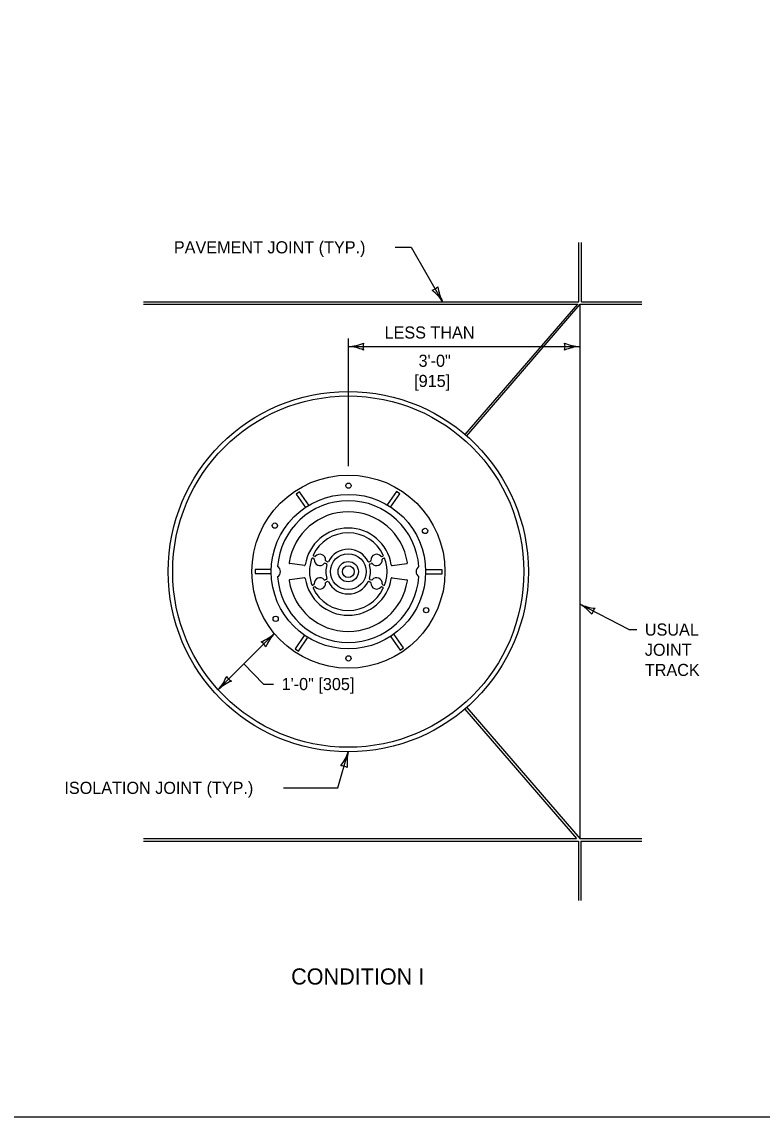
# Model space of a CAD drawing. Extents: x 49991.4 to 50021, y 49987.6 to 50011.4.
# Drawn here: x 50006.05 to 50009.72, y 49987.8 to 49993.22 of the extents above; entities that cross this region are included whole.
import ezdxf

# ---------------------------------------------------------------- set-up
doc = ezdxf.new("R2010")
doc.units = 0
for name, color, linetype in [('Level 1', 7, 'Continuous'), ('Level 15', 7, 'Continuous'), ('Level 2', 7, 'Continuous'), ('Level 3', 7, 'Continuous'), ('Level 62', 7, 'Continuous'), ('W35', 7, 'Continuous')]:
    doc.layers.add(name, color=color, linetype=linetype)

msp = doc.modelspace()

# ---------------------------------------------------------------- linework, layer by layer
at = {"layer": 'Level 1'}
for p, q in [((50008.8099, 49991.838), (50008.8099, 49992.1307)), ((50008.8219, 49991.838), (50008.8219, 49992.1307)), ((50006.6519, 49991.838), (50008.8099, 49991.838)), ((50006.6519, 49991.826), (50008.8044, 49991.826)), ((50008.2465, 49991.1797), (50008.8044, 49991.826)), ((50008.2536, 49991.1736), (50008.8167, 49991.826)), ((50008.8146, 49991.8236), (50008.8146, 49989.1782)), ((50008.8167, 49991.826), (50009.1209, 49991.826)), ((50008.8219, 49991.838), (50009.1209, 49991.838)), ((50007.4491, 49990.5314), (50007.3769, 49990.5416)), ((50007.4961, 49990.5654), (50007.4907, 49990.5676)), ((50007.5004, 49990.5759), (50007.495, 49990.5781)), ((50007.5591, 49990.5393), (50007.5523, 49990.5421)), ((50007.5635, 49990.5498), (50007.5566, 49990.5526)), ((50007.77, 49990.5498), (50007.7768, 49990.5526)), ((50007.7743, 49990.5393), (50007.7812, 49990.5421)), ((50007.833, 49990.5759), (50007.8385, 49990.5781)), ((50007.8374, 49990.5654), (50007.8428, 49990.5676)), ((50007.8844, 49990.5314), (50007.9566, 49990.5416)), ((50007.4491, 49990.4703), (50007.3769, 49990.4601)), ((50007.4961, 49990.4363), (50007.4907, 49990.4341)), ((50007.5591, 49990.4624), (50007.5523, 49990.4596)), ((50007.5635, 49990.4519), (50007.5566, 49990.4491)), ((50007.77, 49990.4519), (50007.7768, 49990.4491)), ((50007.7743, 49990.4624), (50007.7812, 49990.4596)), ((50007.8374, 49990.4363), (50007.8428, 49990.4341)), ((50007.8844, 49990.4703), (50007.9566, 49990.4601)), ((50007.5004, 49990.4258), (50007.495, 49990.4236)), ((50007.833, 49990.4258), (50007.8385, 49990.4236)), ((50008.2445, 49989.8203), (50008.7986, 49989.1783)), ((50008.2536, 49989.8281), (50008.8145, 49989.1783)), ((50006.6519, 49989.1783), (50008.7986, 49989.1783)), ((50006.6519, 49989.1663), (50008.8073, 49989.1663)), ((50008.8073, 49989.1663), (50008.8073, 49988.871)), ((50008.8145, 49989.1783), (50009.1209, 49989.1783)), ((50008.8193, 49989.1663), (50009.1209, 49989.1663)), ((50008.8193, 49989.1663), (50008.8193, 49988.871))]:
    msp.add_line(p, q, dxfattribs=at)
msp.add_lwpolyline([(49999.3835, 49998.9992), (50016.7501, 49998.9992), (50016.7501, 49987.7988), (49999.3835, 49987.7988)], close=True, dxfattribs=at)
for points in [[(50007.4706, 49990.8307), (50007.4246, 49990.8963), (50007.4082, 49990.8848), (50007.4542, 49990.8192)], [(50007.4706, 49990.8307), (50007.4246, 49990.8963), (50007.4082, 49990.8848), (50007.4542, 49990.8192)], [(50007.8755, 49990.8208), (50007.9215, 49990.8864), (50007.9051, 49990.8979), (50007.8591, 49990.8323)], [(50007.8755, 49990.8208), (50007.9215, 49990.8864), (50007.9051, 49990.8979), (50007.8591, 49990.8323)], [(50007.285, 49990.5113), (50007.2049, 49990.5113), (50007.2049, 49990.4913), (50007.285, 49990.4913)], [(50008.0524, 49990.4903), (50008.1325, 49990.4903), (50008.1325, 49990.5103), (50008.0524, 49990.5103)], [(50007.4488, 49990.1844), (50007.4029, 49990.1188), (50007.4193, 49990.1073), (50007.4652, 49990.173)], [(50007.4488, 49990.1844), (50007.4029, 49990.1188), (50007.4193, 49990.1073), (50007.4652, 49990.173)], [(50007.8782, 49990.1784), (50007.9242, 49990.1127), (50007.9406, 49990.1242), (50007.8946, 49990.1898)], [(50007.8782, 49990.1784), (50007.9242, 49990.1127), (50007.9406, 49990.1242), (50007.8946, 49990.1898)]]:
    msp.add_lwpolyline(points, dxfattribs=at)
for centre, radius in [((50007.6667, 49990.5009), 0.8927), ((50007.6667, 49990.5009), 0.8702), ((50007.6676, 49990.5011), 0.4784), ((50007.6676, 49990.5011), 0.4784), ((50007.6676, 49990.9269), 0.0131), ((50007.6676, 49990.5011), 0.3827), ((50007.6676, 49990.5011), 0.3827), ((50007.303, 49990.7289), 0.0131), ((50008.0475, 49990.7025), 0.0131), ((50007.6667, 49990.5009), 0.0888), ((50007.6667, 49990.5009), 0.0503), ((50007.6667, 49990.5009), 0.0293), ((50008.0528, 49990.3102), 0.0131), ((50007.307, 49990.267), 0.0131), ((50007.6676, 49990.0711), 0.0131)]:
    msp.add_circle(centre, radius, dxfattribs=at)
for centre, radius, start, end in [((50007.6667, 49990.5009), 0.3512, 4.1368, 175.8632), ((50007.6667, 49990.5009), 0.2965, 8.7492, 171.2508), ((50007.6667, 49990.5009), 0.216, 8.9977, 171.0023), ((50007.6667, 49990.5009), 0.1922, 90, 154.6354), ((50007.6667, 49990.5009), 0.1922, 25.3646, 90), ((50007.6667, 49990.5009), 0.1107, 90, 152.7811), ((50007.6667, 49990.5009), 0.1107, 27.2189, 90), ((50007.3774, 49990.5454), 0.00383, 171.2515, 262.0006), ((50007.6667, 49990.5009), 0.1922, 160.3645, 179.9999), ((50007.4892, 49990.5642), 0.00374, 67.5005, 160.3653), ((50007.4964, 49990.5816), 0.00374, 154.6345, 247.5005), ((50007.4947, 49990.5619), 0.00374, 354.7032, 67.5005), ((50007.5264, 49990.559), 0.0281, 174.704, 320.2958), ((50007.5019, 49990.5793), 0.00374, 247.5005, 320.2976), ((50007.5264, 49990.559), 0.0281, 354.7044, 140.2958), ((50007.5509, 49990.5387), 0.00374, 67.5005, 140.2976), ((50007.5581, 49990.5561), 0.00374, 174.7032, 247.5005), ((50007.5649, 49990.5532), 0.00374, 247.5005, 332.7814), ((50007.7685, 49990.5532), 0.00374, 207.2186, 292.4995), ((50007.7754, 49990.5561), 0.00374, 292.501, 5.2969), ((50007.8071, 49990.559), 0.0281, 39.7042, 185.2956), ((50007.7826, 49990.5387), 0.00374, 39.7034, 112.501), ((50007.8071, 49990.559), 0.0281, 219.7042, 5.2961), ((50007.8316, 49990.5793), 0.00374, 219.7034, 292.501), ((50007.8388, 49990.5619), 0.00374, 112.501, 185.2969), ((50007.837, 49990.5816), 0.00374, 292.501, 25.3655), ((50007.8442, 49990.5642), 0.00374, 19.6347, 112.501), ((50007.6667, 49990.5009), 0.1922, 0, 19.6355), ((50007.956, 49990.5454), 0.00383, 277.9994, 8.7485), ((50007.3006, 49990.5009), 0.0299, 302.0467, 57.9533), ((50007.4496, 49990.5352), 0.00383, 262.0006, 351.0014), ((50007.6667, 49990.5009), 0.1922, 179.9999, 199.6354), ((50007.6667, 49990.5009), 0.1107, 162.2189, 180), ((50007.6667, 49990.5009), 0.1107, 180, 197.781), ((50007.5577, 49990.5358), 0.00374, 342.2187, 67.5005), ((50007.7757, 49990.5358), 0.00374, 112.4995, 197.7818), ((50007.6667, 49990.5009), 0.1107, 0, 17.7811), ((50007.6667, 49990.5009), 0.1107, 342.2189, 0), ((50007.6667, 49990.5009), 0.1922, 340.3645, 0), ((50007.8838, 49990.5352), 0.00383, 188.9986, 277.9994), ((50008.0328, 49990.5009), 0.0299, 122.0469, 237.9531), ((50007.6667, 49990.5009), 0.3512, 184.1368, 355.8632), ((50007.3774, 49990.4563), 0.00383, 97.9994, 188.7485), ((50007.6667, 49990.5009), 0.2965, 188.7492, 351.2509), ((50007.4496, 49990.4665), 0.00383, 8.9986, 97.9994), ((50007.6667, 49990.5009), 0.216, 188.9977, 351.0024), ((50007.4892, 49990.4375), 0.00374, 199.6347, 292.4995), ((50007.4947, 49990.4398), 0.00374, 292.4995, 5.2968), ((50007.5264, 49990.4427), 0.0281, 39.7042, 185.296), ((50007.5264, 49990.4427), 0.0281, 219.7042, 5.2956), ((50007.5509, 49990.4631), 0.00374, 219.7024, 292.4995), ((50007.5581, 49990.4457), 0.00374, 112.4995, 185.2968), ((50007.5577, 49990.4659), 0.00374, 292.4995, 17.7813), ((50007.5649, 49990.4485), 0.00374, 27.2186, 112.4995), ((50007.6667, 49990.5009), 0.1107, 207.2189, 270), ((50007.6667, 49990.5009), 0.1107, 270, 332.7811), ((50007.7685, 49990.4485), 0.00374, 67.5005, 152.7814), ((50007.7757, 49990.4659), 0.00374, 162.2182, 247.5005), ((50007.7754, 49990.4457), 0.00374, 354.7031, 67.499), ((50007.8071, 49990.4427), 0.0281, 174.7044, 320.2958), ((50007.7826, 49990.4631), 0.00374, 247.499, 320.2966), ((50007.8071, 49990.4427), 0.0281, 354.7039, 140.2958), ((50007.8388, 49990.4398), 0.00374, 174.7031, 247.499), ((50007.8442, 49990.4375), 0.00374, 247.499, 340.3653), ((50007.8838, 49990.4665), 0.00383, 82.0006, 171.0014), ((50007.956, 49990.4563), 0.00383, 351.2515, 82.0006), ((50007.4964, 49990.4201), 0.00374, 112.4995, 205.3655), ((50007.6667, 49990.5009), 0.1922, 205.3646, 270), ((50007.5019, 49990.4224), 0.00374, 39.7024, 112.4995), ((50007.6667, 49990.5009), 0.1922, 270, 334.6354), ((50007.8316, 49990.4224), 0.00374, 67.499, 140.2966), ((50007.837, 49990.4201), 0.00374, 334.6345, 67.499)]:
    msp.add_arc(centre, radius, start, end, dxfattribs=at)
at = {"layer": 'Level 15'}
for q in [(50008.8146, 49990.3397), (50009.0967, 49990.214)]:
    msp.add_line((50009.0567, 49990.214), q, dxfattribs=at)
at = {"layer": 'Level 2'}
msp.add_line((50007.3003, 49990.1945), (50007.0222, 49989.9164), dxfattribs=at)
msp.add_lwpolyline([(50007.3453, 49989.4299), (50007.6157, 49989.4299), (50007.6667, 49989.6082)], dxfattribs=at)
at = {"layer": 'Level 3'}
for p, q in [((50007.8987, 49992.1077), (50007.9787, 49992.1077)), ((50007.9787, 49992.1077), (50008.1344, 49991.838)), ((50007.6667, 49991.6557), (50007.6667, 49991.0242)), ((50007.6667, 49991.6157), (50008.8146, 49991.6157)), ((50007.1495, 49990.0437), (50007.2463, 49989.9441)), ((50007.2463, 49989.9441), (50007.2965, 49989.9441))]:
    msp.add_line(p, q, dxfattribs=at)
for centre, radius, start, end in [((50008.0703, 49991.9491), 0.0548, 282.1388, 317.8612), ((50008.3313, 49991.9412), 0.2223, 187.456, 207.6395), ((50007.9386, 49991.7117), 0.233, 32.8273, 52.0772), ((50007.6552, 49991.8484), 0.233, 272.8273, 292.0772), ((50007.7949, 49991.6157), 0.0548, 162.1388, 197.8612), ((50008.8238, 49991.8378), 0.2223, 247.456, 267.6395), ((50008.6864, 49991.6157), 0.0548, 342.1388, 17.8612), ((50007.6576, 49991.3935), 0.2223, 67.456, 87.6395), ((50008.8261, 49991.383), 0.233, 92.8273, 112.0772), ((50008.7041, 49990.1468), 0.2223, 40.0146, 60.1982), ((50008.9116, 49990.5515), 0.233, 245.3859, 264.6358), ((50008.9284, 49990.2806), 0.0548, 134.6975, 170.4198), ((50007.1497, 49990.3581), 0.2223, 292.456, 312.6395), ((50007.473, 49990.0381), 0.233, 137.8273, 157.0772), ((50007.2096, 49990.1038), 0.0548, 27.1388, 62.8612), ((50006.8495, 49990.0728), 0.233, 317.8273, 337.0772), ((50007.1728, 49989.7528), 0.2223, 112.456, 132.6395), ((50007.1128, 49990.007), 0.0548, 207.1388, 242.8612), ((50007.4557, 49989.6781), 0.2223, 321.4901, 341.6737), ((50007.8936, 49989.5552), 0.233, 166.8614, 186.1113), ((50007.6315, 49989.4849), 0.0548, 56.173, 91.8953)]:
    msp.add_arc(centre, radius, start, end, dxfattribs=at)
at = {"layer": 'Level 62'}
msp.add_line((50008.8073, 49989.1663), (50008.8073, 49988.871), dxfattribs=at)
at = {"layer": 'W35'}
for points in [[(50007.285, 49990.5113), (50007.2049, 49990.5113), (50007.2049, 49990.4913), (50007.285, 49990.4913)], [(50008.0524, 49990.4903), (50008.1325, 49990.4903), (50008.1325, 49990.5103), (50008.0524, 49990.5103)]]:
    msp.add_lwpolyline(points, dxfattribs=at)

# ---------------------------------------------------------------- texts
at = {"layer": 'Level 2'}
for s, height, p in [('PAVEMENT JOINT (TYP.)', 0.06, (50006.8024, 49992.0777)), ('LESS THAN', 0.06, (50007.8466, 49991.6557)), ('3\'-0"', 0.06, (50008.0151, 49991.5157)), ('[915]', 0.06, (50007.9934, 49991.4157)), ('USUAL', 0.06, (50009.1367, 49990.184)), ('JOINT', 0.06, (50009.1367, 49990.084)), ('TRACK', 0.06, (50009.1367, 49989.984)), ('1\'-0" [305]', 0.06, (50007.3365, 49989.9141)), ('CONDITION I', 0.08, (50007.3836, 49988.4555))]:
    msp.add_text(s, height=height, dxfattribs=at).set_placement(p)
msp.add_text('ISOLATION JOINT (TYP.)', height=0.06, rotation=360, dxfattribs=at).set_placement((50006.2599, 49989.3999))

doc.saveas('drawing.dxf')
